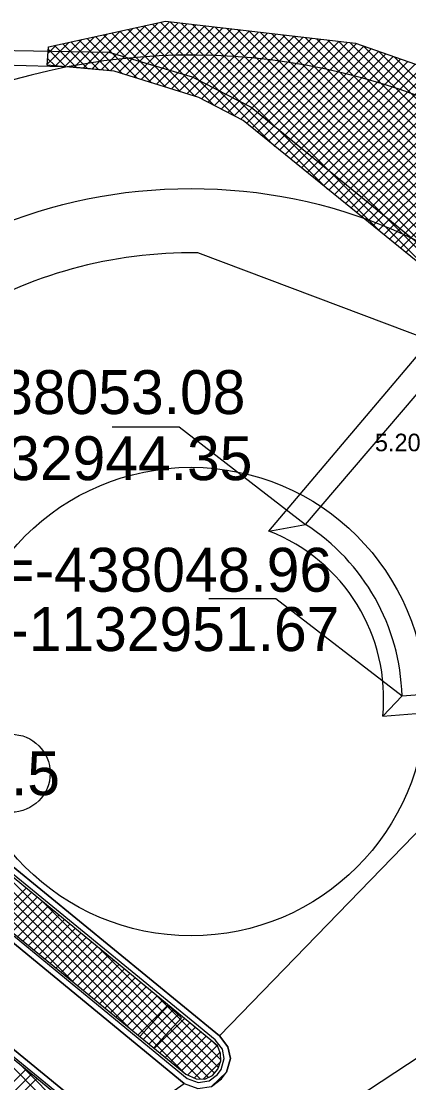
# Model space of a CAD drawing. Extents: x -438410 to -437811, y -1133174 to -1132817.
# Drawn here: x -438065.2 to -438048.68, y -1132968.19 to -1132922.87 of the extents above; entities that cross this region are included whole.
import ezdxf

# ---------------------------------------------------------------- set-up
doc = ezdxf.new("R2010")
doc.units = 0
for name, color, linetype in [('10 - legenda', 7, 'Continuous'), ('Vrstva 1', 7, 'Continuous'), ('Vrstva 5', 7, 'Continuous')]:
    doc.layers.add(name, color=color, linetype=linetype)

msp = doc.modelspace()

# ---------------------------------------------------------------- linework, layer by layer
at = {"layer": '10 - legenda'}
for p, q in [((-438061.797, -1132924.949), (-438059.905, -1132923.057)), ((-438061.407, -1132924.983), (-438059.361, -1132922.937)), ((-438061.056, -1132925.057), (-438058.888, -1132922.889)), ((-438060.733, -1132925.157), (-438058.508, -1132922.933)), ((-438060.409, -1132925.258), (-438058.128, -1132922.977)), ((-438060.085, -1132925.358), (-438057.748, -1132923.021)), ((-438059.955, -1132923.068), (-438056.099, -1132926.924)), ((-438059.761, -1132925.459), (-438057.368, -1132923.066)), ((-438059.608, -1132922.991), (-438054.387, -1132928.212)), ((-438059.26, -1132922.915), (-438052.139, -1132930.036)), ((-438058.858, -1132922.892), (-438049.891, -1132931.86)), ((-438058.378, -1132922.948), (-438047.642, -1132933.684)), ((-438057.898, -1132923.004), (-438045.394, -1132935.507)), ((-438057.418, -1132923.06), (-438043.146, -1132937.331)), ((-438063.357, -1132924.812), (-438062.08, -1132923.535)), ((-438062.967, -1132924.846), (-438061.536, -1132923.415)), ((-438062.577, -1132924.881), (-438060.992, -1132923.296)), ((-438062.187, -1132924.915), (-438060.449, -1132923.176)), ((-438062.042, -1132923.527), (-438060.266, -1132925.302)), ((-438061.694, -1132923.45), (-438059.651, -1132925.493)), ((-438061.346, -1132923.374), (-438059.036, -1132925.684)), ((-438060.999, -1132923.297), (-438058.42, -1132925.875)), ((-438060.651, -1132923.221), (-438057.805, -1132926.067)), ((-438060.303, -1132923.144), (-438056.991, -1132926.457)), ((-438059.438, -1132925.56), (-438056.988, -1132923.11)), ((-438059.114, -1132925.66), (-438056.608, -1132923.154)), ((-438058.79, -1132925.761), (-438056.228, -1132923.198)), ((-438058.467, -1132925.861), (-438055.848, -1132923.242)), ((-438058.143, -1132925.962), (-438055.468, -1132923.286)), ((-438057.819, -1132926.062), (-438055.087, -1132923.331)), ((-438057.515, -1132926.182), (-438054.707, -1132923.375)), ((-438057.236, -1132926.328), (-438054.327, -1132923.419)), ((-438056.958, -1132926.474), (-438053.947, -1132923.463)), ((-438056.938, -1132923.116), (-438040.898, -1132939.155)), ((-438056.68, -1132926.62), (-438053.567, -1132923.507)), ((-438056.458, -1132923.171), (-438038.65, -1132940.979)), ((-438056.401, -1132926.766), (-438053.187, -1132923.551)), ((-438055.978, -1132923.227), (-438036.402, -1132942.803)), ((-438055.497, -1132923.283), (-438022.332, -1132956.448)), ((-438055.017, -1132923.339), (-438022.12, -1132956.236)), ((-438054.537, -1132923.394), (-438021.908, -1132956.024)), ((-438054.057, -1132923.45), (-438021.696, -1132955.812)), ((-438053.577, -1132923.506), (-438021.483, -1132955.6)), ((-438064.097, -1132924.703), (-438063.168, -1132923.774)), ((-438064.065, -1132924.247), (-438063.712, -1132923.894)), ((-438063.781, -1132923.909), (-438062.832, -1132924.858)), ((-438063.747, -1132924.778), (-438062.624, -1132923.655)), ((-438063.433, -1132923.833), (-438062.367, -1132924.899)), ((-438063.085, -1132923.756), (-438061.901, -1132924.94)), ((-438062.738, -1132923.68), (-438061.436, -1132924.981)), ((-438062.39, -1132923.603), (-438060.882, -1132925.111)), ((-438056.123, -1132926.911), (-438052.807, -1132923.596)), ((-438055.844, -1132927.057), (-438052.427, -1132923.64)), ((-438055.595, -1132927.232), (-438052.047, -1132923.684)), ((-438055.361, -1132927.422), (-438051.667, -1132923.728)), ((-438055.126, -1132927.612), (-438051.287, -1132923.772)), ((-438054.892, -1132927.802), (-438050.915, -1132923.825)), ((-438054.658, -1132927.992), (-438050.6, -1132923.935)), ((-438053.097, -1132923.562), (-438021.271, -1132955.388)), ((-438052.617, -1132923.618), (-438021.059, -1132955.176)), ((-438052.137, -1132923.673), (-438020.847, -1132954.964)), ((-438051.657, -1132923.729), (-438020.635, -1132954.752)), ((-438051.177, -1132923.785), (-438020.423, -1132954.539)), ((-438050.605, -1132923.933), (-438020.21, -1132954.327)), ((-438064.08, -1132924.458), (-438063.762, -1132924.776)), ((-438064.052, -1132924.062), (-438063.297, -1132924.817)), ((-438054.424, -1132928.182), (-438050.286, -1132924.045)), ((-438054.189, -1132928.372), (-438049.972, -1132924.155)), ((-438053.955, -1132928.562), (-438049.658, -1132924.265)), ((-438053.721, -1132928.752), (-438049.344, -1132924.375)), ((-438049.952, -1132924.162), (-438020.004, -1132954.109)), ((-438049.298, -1132924.391), (-438019.942, -1132953.747)), ((-438053.487, -1132928.942), (-438049.029, -1132924.485)), ((-438053.252, -1132929.132), (-438048.715, -1132924.595)), ((-438053.018, -1132929.322), (-438048.401, -1132924.705)), ((-438052.784, -1132929.512), (-438048.087, -1132924.815)), ((-438052.55, -1132929.702), (-438047.773, -1132924.925)), ((-438052.315, -1132929.892), (-438047.459, -1132925.035)), ((-438052.081, -1132930.082), (-438047.144, -1132925.146)), ((-438051.847, -1132930.272), (-438046.83, -1132925.256)), ((-438051.613, -1132930.462), (-438046.516, -1132925.366)), ((-438051.379, -1132930.652), (-438046.202, -1132925.476)), ((-438051.144, -1132930.843), (-438045.888, -1132925.586)), ((-438050.91, -1132931.033), (-438045.573, -1132925.696)), ((-438050.676, -1132931.223), (-438045.259, -1132925.806)), ((-438050.442, -1132931.413), (-438044.945, -1132925.916)), ((-438050.207, -1132931.603), (-438044.631, -1132926.026)), ((-438049.973, -1132931.793), (-438044.317, -1132926.136)), ((-438049.739, -1132931.983), (-438044.003, -1132926.246)), ((-438049.505, -1132932.173), (-438043.688, -1132926.356)), ((-438049.27, -1132932.363), (-438043.374, -1132926.467)), ((-438049.036, -1132932.553), (-438043.06, -1132926.577)), ((-438048.802, -1132932.743), (-438042.746, -1132926.687)), ((-438054.642, -1132944.634), (-438047.59, -1132936.293)), ((-438053.084, -1132944.349), (-438047.411, -1132937.701)), ((-438054.642, -1132944.634), (-438053.084, -1132944.349)), ((-438048.965, -1132951.673), (-438040.286, -1132950.986)), ((-438048.965, -1132951.673), (-438049.786, -1132952.54)), ((-438049.786, -1132952.54), (-438039.513, -1132951.677)), ((-438074.096, -1132952.771), (-438062.879, -1132963.988)), ((-438073.575, -1132952.868), (-438060.544, -1132965.899)), ((-438071.497, -1132954.522), (-438058.21, -1132967.809)), ((-438069.088, -1132956.507), (-438057.563, -1132968.032)), ((-438066.679, -1132958.492), (-438057.213, -1132967.958)), ((-438066.3, -1132961.189), (-438064.993, -1132959.881)), ((-438066.067, -1132961.38), (-438064.76, -1132960.072)), ((-438065.834, -1132961.571), (-438064.527, -1132960.264)), ((-438065.6, -1132961.761), (-438064.295, -1132960.456)), ((-438065.367, -1132961.952), (-438064.062, -1132960.647)), ((-438064.269, -1132960.477), (-438056.966, -1132967.78)), ((-438065.134, -1132962.143), (-438063.829, -1132960.839)), ((-438064.9, -1132962.334), (-438063.597, -1132961.031)), ((-438064.667, -1132962.525), (-438063.364, -1132961.222)), ((-438064.434, -1132962.716), (-438063.132, -1132961.414)), ((-438064.2, -1132962.907), (-438062.899, -1132961.606)), ((-438063.967, -1132963.098), (-438062.666, -1132961.797)), ((-438063.734, -1132963.289), (-438062.434, -1132961.989)), ((-438063.5, -1132963.48), (-438062.201, -1132962.181)), ((-438063.267, -1132963.671), (-438061.969, -1132962.372)), ((-438061.86, -1132962.461), (-438056.79, -1132967.532)), ((-438063.034, -1132963.862), (-438061.736, -1132962.564)), ((-438062.8, -1132964.053), (-438061.503, -1132962.756)), ((-438062.567, -1132964.244), (-438061.271, -1132962.947)), ((-438062.334, -1132964.434), (-438061.038, -1132963.139)), ((-438062.1, -1132964.625), (-438060.806, -1132963.33)), ((-438061.867, -1132964.816), (-438060.573, -1132963.522)), ((-438061.634, -1132965.007), (-438060.34, -1132963.714)), ((-438061.4, -1132965.198), (-438060.108, -1132963.905)), ((-438061.167, -1132965.389), (-438059.875, -1132964.097)), ((-438060.934, -1132965.58), (-438059.642, -1132964.289)), ((-438060.7, -1132965.771), (-438059.41, -1132964.48)), ((-438060.467, -1132965.962), (-438059.177, -1132964.672)), ((-438059.451, -1132964.446), (-438056.694, -1132967.203)), ((-438060.234, -1132966.153), (-438058.945, -1132964.864)), ((-438060, -1132966.344), (-438058.712, -1132965.055)), ((-438059.767, -1132966.535), (-438058.479, -1132965.247)), ((-438067.601, -1132965.486), (-438061.398, -1132971.689)), ((-438059.534, -1132966.726), (-438058.247, -1132965.439)), ((-438059.3, -1132966.917), (-438058.014, -1132965.63)), ((-438059.067, -1132967.107), (-438057.782, -1132965.822)), ((-438058.834, -1132967.298), (-438057.549, -1132966.014)), ((-438058.6, -1132967.489), (-438057.316, -1132966.205)), ((-438058.367, -1132967.68), (-438057.084, -1132966.397)), ((-438058.12, -1132967.857), (-438056.854, -1132966.591)), ((-438057.042, -1132966.431), (-438056.81, -1132966.663)), ((-438057.827, -1132967.988), (-438056.723, -1132966.884)), ((-438065.192, -1132967.471), (-438061.248, -1132971.415)), ((-438057.45, -1132968.036), (-438056.707, -1132967.293)), ((-438066.297, -1132968.922), (-438065.002, -1132967.628)), ((-438066.063, -1132969.113), (-438064.77, -1132967.819)), ((-438065.83, -1132969.304), (-438064.537, -1132968.011))]:
    msp.add_line(p, q, dxfattribs=at)
for points in [[(-438064.046, -1132923.967), (-438059.054, -1132922.87), (-438050.953, -1132923.811), (-438023.373, -1132933.474), (-438021.008, -1132936.054), (-438019.535, -1132939.812), (-438019.088, -1132943.791), (-438019.045, -1132948.5), (-438020.007, -1132954.124), (-438035.014, -1132969.123), (-438035.457, -1132968.667), (-438032.713, -1132965.089), (-438031.357, -1132962.656), (-438030.164, -1132959.335), (-438029.71, -1132956.158), (-438029.67, -1132953.257), (-438030.136, -1132951.258), (-438031.147, -1132948.836), (-438032.937, -1132946), (-438035.111, -1132943.85), (-438055.747, -1132927.108), (-438057.633, -1132926.12), (-438061.247, -1132924.998), (-438064.1, -1132924.747)], [(-438073.176, -1132952.717), (-438073.784, -1132952.418), (-438074.41, -1132952.486), (-438074.85, -1132952.773), (-438075.195, -1132953.283), (-438075.246, -1132953.861), (-438075.079, -1132954.279), (-438074.905, -1132954.521), (-438058.255, -1132968.222), (-438057.68, -1132968.43), (-438057.085, -1132968.345), (-438056.658, -1132968.016), (-438056.447, -1132967.73), (-438056.287, -1132967.153), (-438056.391, -1132966.651), (-438056.752, -1132966.178)], [(-438073.312, -1132952.929), (-438073.829, -1132952.674), (-438074.323, -1132952.728), (-438074.671, -1132952.955), (-438074.951, -1132953.369), (-438074.991, -1132953.824), (-438074.858, -1132954.158), (-438074.721, -1132954.349), (-438058.129, -1132968.002), (-438057.653, -1132968.174), (-438057.186, -1132968.107), (-438056.838, -1132967.84), (-438056.676, -1132967.619), (-438056.545, -1132967.145), (-438056.625, -1132966.757), (-438056.933, -1132966.353)], [(-438073.336, -1132953.006), (-438073.771, -1132952.754), (-438074.222, -1132952.777), (-438074.55, -1132952.961), (-438074.787, -1132953.251), (-438074.894, -1132953.556), (-438074.886, -1132953.915), (-438074.756, -1132954.167), (-438074.665, -1132954.344), (-438058.189, -1132967.826), (-438057.747, -1132968.024), (-438057.373, -1132968.039), (-438057.044, -1132967.871), (-438056.815, -1132967.604), (-438056.693, -1132967.253), (-438056.701, -1132966.94), (-438056.831, -1132966.611), (-438057.037, -1132966.436)], [(-438077.661, -1132956.827), (-438078.269, -1132956.528), (-438078.895, -1132956.595), (-438079.335, -1132956.883), (-438079.68, -1132957.392), (-438079.731, -1132957.971), (-438079.564, -1132958.389), (-438079.39, -1132958.631), (-438062.73, -1132972.34), (-438062.14, -1132972.492), (-438061.627, -1132972.368), (-438061.215, -1132972.034), (-438060.994, -1132971.709), (-438060.884, -1132971.265), (-438060.96, -1132970.785), (-438061.221, -1132970.3)], [(-438077.797, -1132957.039), (-438078.314, -1132956.784), (-438078.808, -1132956.837), (-438079.156, -1132957.065), (-438079.436, -1132957.479), (-438079.476, -1132957.933), (-438079.343, -1132958.268), (-438079.206, -1132958.459), (-438062.614, -1132972.112), (-438062.138, -1132972.234), (-438061.741, -1132972.138), (-438061.401, -1132971.863), (-438061.226, -1132971.605), (-438061.139, -1132971.254), (-438061.2, -1132970.867), (-438061.418, -1132970.463)], [(-438077.71, -1132957.158), (-438078.145, -1132956.906), (-438078.595, -1132956.929), (-438078.923, -1132957.112), (-438079.16, -1132957.403), (-438079.267, -1132957.708), (-438079.259, -1132958.067), (-438079.13, -1132958.319), (-438079.039, -1132958.496), (-438062.563, -1132971.977), (-438062.12, -1132972.11), (-438061.823, -1132972.054), (-438061.58, -1132971.932), (-438061.339, -1132971.61), (-438061.243, -1132971.404), (-438061.235, -1132971.091), (-438061.312, -1132970.763), (-438061.41, -1132970.587)]]:
    msp.add_lwpolyline(points, close=True, dxfattribs=at)
for points in [[(-438073.176, -1132952.717), (-438056.752, -1132966.178), (-438035.111, -1132943.85), (-438055.747, -1132927.108), (-438057.633, -1132926.12), (-438061.247, -1132924.998), (-438062.981, -1132924.836), (-438065.997, -1132924.747)], [(-438061.33, -1132940.191), (-438058.466, -1132940.191), (-438053.084, -1132944.349)], [(-438047.351, -1132977.847), (-438035.024, -1132966.82), (-438033.236, -1132964.241), (-438032.047, -1132961.955), (-438030.901, -1132957.963), (-438030.66, -1132955.437), (-438030.712, -1132952.747), (-438030.075, -1132952.687), (-438030.136, -1132951.258), (-438031.431, -1132948.289), (-438033.325, -1132945.529), (-438035.111, -1132943.85), (-438056.752, -1132966.178), (-438056.391, -1132966.651), (-438056.287, -1132967.153), (-438056.447, -1132967.73), (-438057.085, -1132968.345)], [(-438057.21, -1132947.514), (-438054.346, -1132947.514), (-438048.965, -1132951.673)], [(-438077.661, -1132956.827), (-438061.221, -1132970.3), (-438058.255, -1132968.222), (-438074.905, -1132954.521)]]:
    msp.add_lwpolyline(points, dxfattribs=at)
msp.add_circle((-438065.636, -1132954.975), 1.666, dxfattribs=at)
for centre, radius, start, end in [((-438057.962, -1132951.913), 9, 1.5299, 57.1856), ((-438057.428, -1132951.79), 7.679, 354.3931, 68.731)]:
    msp.add_arc(centre, radius, start, end, dxfattribs=at)
at = {"layer": 'Vrstva 1'}
for p, q in [((-438057.684, -1132932.736), (-438045.528, -1132937.343)), ((-438042.628, -1132963.381), (-438053.487, -1132970.529))]:
    msp.add_line(p, q, dxfattribs=at)
for radius in [21.902, 10]:
    msp.add_circle((-438057.962, -1132951.913), radius, dxfattribs=at)
for centre, radius, start, end in [((-438057.962, -1132951.913), 27.6, 21.7557, 127.458), ((-438057.961, -1132951.909), 19.15, 89.1789, 121.5091), ((-438057.962, -1132951.913), 27.6, 285.1936, 325.11)]:
    msp.add_arc(centre, radius, start, end, dxfattribs=at)
at = {"layer": 'Vrstva 5'}
for points in [[(-438100.102, -1132946.562), (-438096.145, -1132946.087), (-438076.81, -1132928.968), (-438073.152, -1132926.415), (-438070.224, -1132924.975), (-438066.296, -1132924.11), (-438061.467, -1132924.187), (-438057.913, -1132925.24), (-438055.399, -1132926.536), (-438032.541, -1132945.181), (-438030.254, -1132949.067), (-438029.004, -1132953.142), (-438028.985, -1132956.312), (-438029.517, -1132959.914), (-438030.683, -1132962.977), (-438031.923, -1132965.059), (-438033.387, -1132967.52), (-438034.269, -1132968.372), (-438043.912, -1132976.82)], [(-438060.134, -1132966.192), (-438058.945, -1132964.894), (-438058.372, -1132965.42), (-438059.56, -1132966.717)]]:
    msp.add_lwpolyline(points, dxfattribs=at)

# ---------------------------------------------------------------- texts
at = {"layer": '10 - legenda'}
for s, p in [('X=-438053.08', (-438071.467, -1132939.64)), ('Y=-1132944.35', (-438072.563, -1132942.462)), ('X=-438048.96', (-438067.772, -1132947.225)), ('Y=-1132951.67', (-438068.856, -1132949.758))]:
    msp.add_text(s, height=1.875, rotation=360, dxfattribs=at).set_placement(p)
msp.add_text('5.20 ', height=0.75, dxfattribs=at).set_placement((-438050.125, -1132941.228))
at = {"layer": 'Vrstva 5'}
msp.add_text('2.5', height=1.875, dxfattribs=at).set_placement((-438067.037, -1132955.913))

doc.saveas('drawing.dxf')
